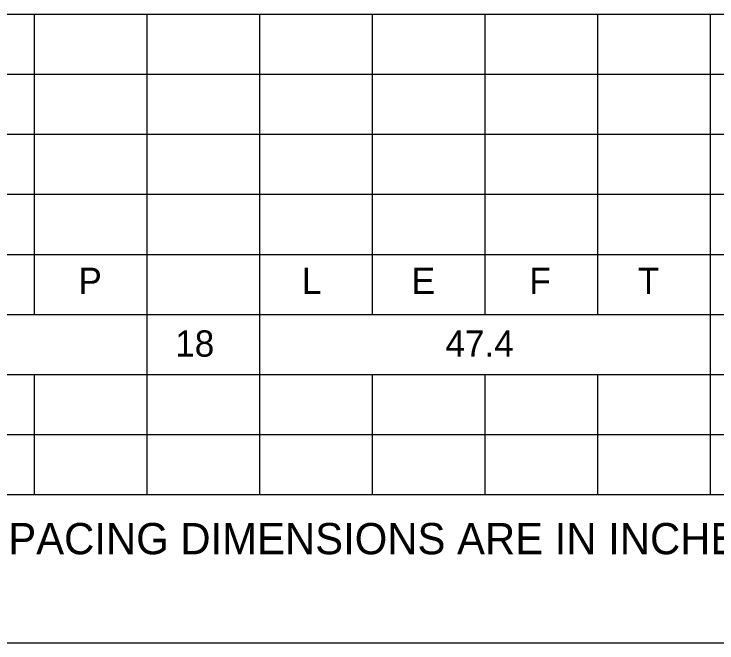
# Model space of a CAD drawing. Extents: x 10268312 to 10268472, y 2142583 to 2142688.
# Drawn here: x 10268336.45 to 10268355.16, y 2142640.28 to 2142657.03 of the extents above; entities that cross this region are included whole.
import ezdxf

# ---------------------------------------------------------------- set-up
doc = ezdxf.new("R2010")
doc.units = 0
for name, color, linetype in [('SheetBorder_dp', 7, 'Continuous'), ('SumBoxLines_dp', 7, 'Continuous'), ('SumBoxLinesMin_dp', 7, 'Continuous'), ('TextLabel', 7, 'Continuous'), ('TextNotes', 7, 'Continuous')]:
    doc.layers.add(name, color=color, linetype=linetype)

msp = doc.modelspace()

# ---------------------------------------------------------------- linework, layer by layer
at = {"layer": 'SheetBorder_dp'}
msp.add_line((10268317.73, 2142640.282), (10268471.73, 2142640.282), dxfattribs=at)
at = {"layer": 'SumBoxLines_dp'}
for p, q in [((10268318.48, 2142657.032), (10268393.98, 2142657.032)), ((10268336.98, 2142657.032), (10268336.98, 2142653.832)), ((10268339.98, 2142657.032), (10268339.98, 2142653.832)), ((10268342.98, 2142657.032), (10268342.98, 2142655.432)), ((10268345.98, 2142657.032), (10268345.98, 2142653.832)), ((10268348.98, 2142657.032), (10268348.98, 2142653.832)), ((10268351.98, 2142657.032), (10268351.98, 2142653.832)), ((10268354.98, 2142657.032), (10268354.98, 2142653.832)), ((10268342.98, 2142655.432), (10268342.98, 2142650.632)), ((10268318.48, 2142653.832), (10268393.98, 2142653.832)), ((10268336.98, 2142653.832), (10268336.98, 2142649.032)), ((10268339.98, 2142653.832), (10268339.98, 2142650.632)), ((10268345.98, 2142653.832), (10268345.98, 2142650.632)), ((10268348.98, 2142653.832), (10268348.98, 2142650.632)), ((10268351.98, 2142653.832), (10268351.98, 2142650.632)), ((10268354.98, 2142653.832), (10268354.98, 2142649.032)), ((10268318.48, 2142650.632), (10268393.98, 2142650.632)), ((10268339.98, 2142650.632), (10268339.98, 2142647.432)), ((10268342.98, 2142650.632), (10268342.98, 2142647.432)), ((10268345.98, 2142650.632), (10268345.98, 2142649.032)), ((10268348.98, 2142650.632), (10268348.98, 2142649.032)), ((10268351.98, 2142650.632), (10268351.98, 2142649.032)), ((10268354.98, 2142649.032), (10268354.98, 2142644.232)), ((10268318.48, 2142647.432), (10268393.98, 2142647.432)), ((10268336.98, 2142647.432), (10268336.98, 2142644.232)), ((10268339.98, 2142647.432), (10268339.98, 2142644.232)), ((10268342.98, 2142647.432), (10268342.98, 2142644.232)), ((10268345.98, 2142647.432), (10268345.98, 2142644.232)), ((10268348.98, 2142647.432), (10268348.98, 2142644.232)), ((10268351.98, 2142647.432), (10268351.98, 2142644.232)), ((10268318.48, 2142644.232), (10268393.98, 2142644.232))]:
    msp.add_line(p, q, dxfattribs=at)
at = {"layer": 'SumBoxLinesMin_dp'}
for p, q in [((10268318.48, 2142655.432), (10268393.98, 2142655.432)), ((10268318.48, 2142652.232), (10268393.98, 2142652.232)), ((10268318.48, 2142649.032), (10268393.98, 2142649.032)), ((10268318.48, 2142645.832), (10268393.98, 2142645.832))]:
    msp.add_line(p, q, dxfattribs=at)

# ---------------------------------------------------------------- texts
at = {"layer": 'TextLabel'}
for s, p in [('P', (10268338.16, 2142649.576)), ('L', (10268344.112, 2142649.576)), ('E', (10268347.033, 2142649.576)), ('F', (10268350.168, 2142649.576)), ('T', (10268353.056, 2142649.576)), ('18', (10268340.737, 2142647.907)), ('47.4', (10268347.934, 2142647.907))]:
    msp.add_text(s, height=0.7, dxfattribs=at).set_placement(p)
at = {"layer": 'TextNotes'}
msp.add_text('NOTE:  WIDTH - HORIZONTAL SPACING DIMENSIONS ARE IN INCHES.', height=0.83333, dxfattribs=at).set_placement((10268319.392, 2142642.643))

doc.saveas('drawing.dxf')
